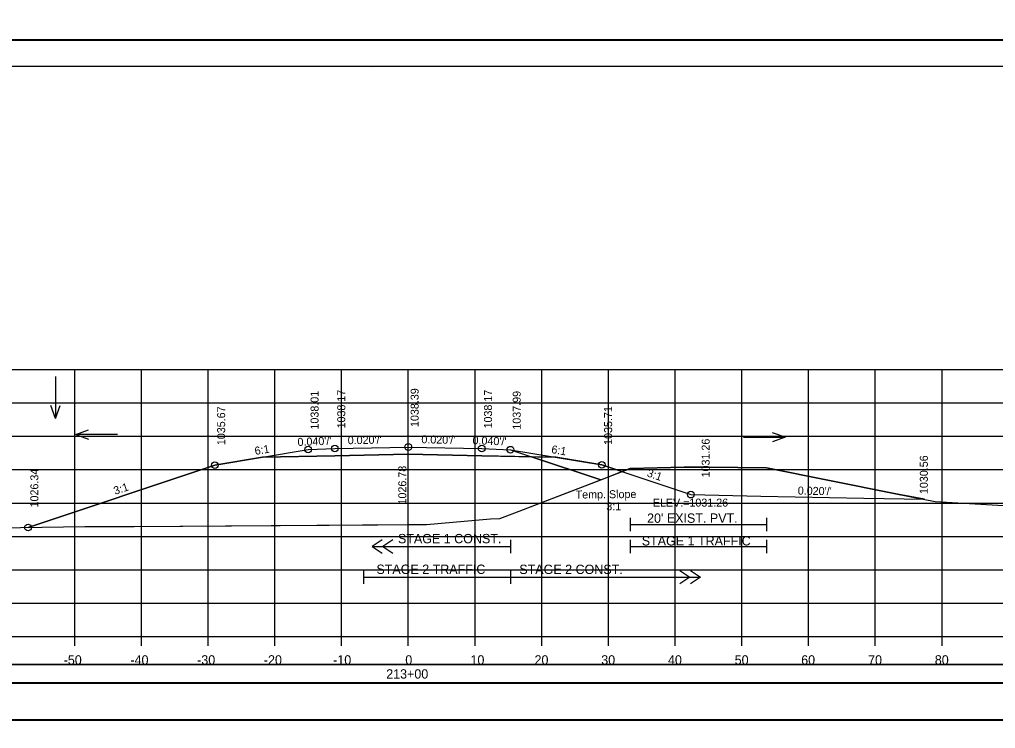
# Model space of a CAD drawing. Extents: x 1370565 to 1374448, y 301010 to 304637.
# Drawn here: x 1373310.5 to 1373456.8, y 302261.9 to 302368.1 of the extents above; entities that cross this region are included whole.
import ezdxf

# ---------------------------------------------------------------- set-up
doc = ezdxf.new("R2010")
doc.units = 0
for name, color, linetype in [('Default', 7, 'Continuous'), ('R_Alt Surface', 7, 'Continuous'), ('R_Axis', 7, 'Continuous'), ('R_Axis Annot', 7, 'Continuous'), ('R_Border', 7, 'Continuous'), ('R_Contours', 7, 'Continuous'), ('R_Drive', 7, 'Continuous'), ('R_Exist Surface', 7, 'Continuous'), ('R_Fin Surface', 7, 'Continuous'), ('R_Grid', 7, 'Continuous'), ('R_No Plot', 7, 'Continuous'), ('R_Water', 7, 'Continuous'), ('R_Water Annot', 7, 'Continuous'), ('R_Xsect Elev', 7, 'Continuous'), ('R_Xsect Slope', 7, 'Continuous')]:
    doc.layers.add(name, color=color, linetype=linetype)

msp = doc.modelspace()

# ---------------------------------------------------------------- linework, layer by layer
at = {"layer": 'Default'}
for points in [[(1373219.61, 302268.69), (1373518.02, 302268.69), (1373518.02, 302271.39), (1373219.61, 302271.39)], [(1373219.61, 302263.11), (1373518.02, 302263.11), (1373518.02, 302268.63), (1373219.61, 302268.63)]]:
    msp.add_lwpolyline(points, close=True, dxfattribs=at)
at = {"layer": 'R_Alt Surface'}
for points in [[(1373346.97, 302302.52), (1373357.81, 302302.73), (1373368.81, 302302.95), (1373379.81, 302302.73), (1373390.91, 302302.51)], [(1373364.9, 302290.14), (1373363.4, 302289.14), (1373364.9, 302288.14)], [(1373363.4, 302289.14), (1373384.11, 302289.14)], [(1373366.5, 302290.14), (1373365, 302289.14), (1373366.5, 302288.14)], [(1373362.11, 302285.56), (1373362.11, 302283.56)], [(1373362.11, 302284.56), (1373384.11, 302284.56)], [(1373384.11, 302285.56), (1373384.11, 302283.56)], [(1373384.11, 302285.56), (1373384.11, 302283.56)], [(1373384.11, 302284.56), (1373412.6, 302284.56)], [(1373409.5, 302285.56), (1373411, 302284.56), (1373409.5, 302283.56)], [(1373411.1, 302285.56), (1373412.6, 302284.56), (1373411.1, 302283.56)]]:
    msp.add_lwpolyline(points, dxfattribs=at)
at = {"layer": 'R_Axis'}
for p, q in [((1373218.81, 302275.65), (1373518.81, 302275.65)), ((1373318.81, 302274.25), (1373318.81, 302275.65)), ((1373328.81, 302274.25), (1373328.81, 302275.65)), ((1373338.81, 302274.25), (1373338.81, 302275.65)), ((1373348.81, 302274.25), (1373348.81, 302275.65)), ((1373358.81, 302274.25), (1373358.81, 302275.65)), ((1373368.81, 302274.25), (1373368.81, 302275.65)), ((1373378.81, 302274.25), (1373378.81, 302275.65)), ((1373388.81, 302274.25), (1373388.81, 302275.65)), ((1373398.81, 302274.25), (1373398.81, 302275.65)), ((1373408.81, 302274.25), (1373408.81, 302275.65)), ((1373418.81, 302274.25), (1373418.81, 302275.65)), ((1373428.81, 302274.25), (1373428.81, 302275.65)), ((1373438.81, 302274.25), (1373438.81, 302275.65)), ((1373448.81, 302274.25), (1373448.81, 302275.65))]:
    msp.add_line(p, q, dxfattribs=at)
for points in [[(1373402.08, 302293.45), (1373402.08, 302291.45)], [(1373422.5, 302293.45), (1373422.5, 302291.45)], [(1373402.08, 302292.45), (1373422.5, 302292.45)], [(1373384.11, 302290.14), (1373384.11, 302288.14)], [(1373402.08, 302290.14), (1373402.08, 302288.14)], [(1373402.08, 302289.14), (1373422.5, 302289.14)], [(1373422.5, 302290.14), (1373422.5, 302288.14)]]:
    msp.add_lwpolyline(points, dxfattribs=at)
at = {"layer": 'R_Border'}
for p, q in [((1373210.81, 302361.11), (1373526.99, 302361.11)), ((1373363.33, 302360.85), (1373363.33, 302360.85)), ((1373363.33, 302360.85), (1373363.33, 302360.85))]:
    msp.add_line(p, q, dxfattribs=at)
at = {"layer": 'R_Contours'}
for p, q in [((1373346.97, 302302.52), (1373339.81, 302301.32)), ((1373397.65, 302299.13), (1373387.29, 302302.58)), ((1373390.91, 302302.51), (1373387.29, 302302.58)), ((1373387.29, 302302.58), (1373397.65, 302299.13)), ((1373397.65, 302299.13), (1373400.83, 302300.35)), ((1373400.83, 302300.35), (1373411.17, 302296.91))]:
    msp.add_line(p, q, dxfattribs=at)
for points in [[(1373387.29, 302302.58), (1373379.81, 302302.73), (1373368.81, 302302.95), (1373357.81, 302302.73), (1373346.97, 302302.52)], [(1373400.83, 302300.35), (1373397.81, 302301.36), (1373390.91, 302302.51)], [(1373339.81, 302301.32), (1373336.37, 302300.17), (1373331.58, 302298.58), (1373319.49, 302294.55), (1373311.81, 302291.99)], [(1373446.17, 302296.21), (1373441.9, 302297.01), (1373422.5, 302300.9), (1373413.89, 302301.01), (1373411.85, 302301.04), (1373410.16, 302301), (1373402.08, 302300.84), (1373400.83, 302300.35)], [(1373311.81, 302291.99), (1373313.93, 302292.02), (1373320.33, 302292.12), (1373327.73, 302292.13), (1373368.81, 302292.43), (1373371.56, 302292.45), (1373381.12, 302293.26), (1373382.52, 302293.32), (1373384.77, 302294.16), (1373397.65, 302299.13)], [(1373411.17, 302296.91), (1373421.67, 302296.7), (1373437.1, 302296.39), (1373446.17, 302296.21)]]:
    msp.add_lwpolyline(points, dxfattribs=at)
at = {"layer": 'R_Drive'}
for points in [[(1373219.61, 302268.74), (1373518.02, 302268.74), (1373518.02, 302271.45), (1373219.61, 302271.45)], [(1373219.61, 302263.22), (1373518.02, 302263.22), (1373518.02, 302268.74), (1373219.61, 302268.74)]]:
    msp.add_lwpolyline(points, close=True, dxfattribs=at)
at = {"layer": 'R_Exist Surface'}
msp.add_lwpolyline([(1373268.65, 302291.32), (1373313.93, 302292.02), (1373320.33, 302292.12), (1373327.73, 302292.13), (1373371.56, 302292.45), (1373381.12, 302293.26), (1373382.52, 302293.32), (1373384.77, 302294.16), (1373402.08, 302300.84), (1373410.16, 302301), (1373411.85, 302301.04), (1373413.89, 302301.01), (1373422.5, 302300.9), (1373441.9, 302297.01), (1373447.77, 302295.9), (1373463.18, 302294.99), (1373467.23, 302294.76), (1373469.74, 302294.76), (1373506.89, 302294.78), (1373511.29, 302294.84), (1373516.55, 302294.89), (1373518.81, 302294.87)], dxfattribs=at)
at = {"layer": 'R_Fin Surface'}
msp.add_line((1373384.11, 302303.64), (1373397.65, 302299.13), dxfattribs=at)
msp.add_lwpolyline([(1373311.81, 302291.99), (1373319.49, 302294.55), (1373331.58, 302298.58), (1373336.37, 302300.17), (1373339.81, 302301.32), (1373353.81, 302303.66), (1373357.81, 302303.82), (1373368.81, 302304.04), (1373379.81, 302303.82), (1373384.11, 302303.64), (1373397.81, 302301.36), (1373411.17, 302296.91), (1373421.67, 302296.7), (1373437.1, 302296.39), (1373446.17, 302296.21)], dxfattribs=at)
at = {"layer": 'R_Grid'}
for p, q in [((1373218.81, 302315.65), (1373518.81, 302315.65)), ((1373318.81, 302275.65), (1373318.81, 302315.65)), ((1373328.81, 302275.65), (1373328.81, 302315.65)), ((1373338.81, 302275.65), (1373338.81, 302315.65)), ((1373348.81, 302275.65), (1373348.81, 302315.65)), ((1373358.81, 302275.65), (1373358.81, 302315.65)), ((1373368.81, 302275.65), (1373368.81, 302315.65)), ((1373378.81, 302275.65), (1373378.81, 302315.65)), ((1373388.81, 302275.65), (1373388.81, 302315.65)), ((1373398.81, 302275.65), (1373398.81, 302315.65)), ((1373408.81, 302275.65), (1373408.81, 302315.65)), ((1373418.81, 302275.65), (1373418.81, 302315.65)), ((1373428.81, 302275.65), (1373428.81, 302315.65)), ((1373438.81, 302275.65), (1373438.81, 302315.65)), ((1373448.81, 302275.65), (1373448.81, 302315.65)), ((1373218.81, 302310.65), (1373518.81, 302310.65)), ((1373218.81, 302305.65), (1373518.81, 302305.65)), ((1373218.81, 302300.65), (1373518.81, 302300.65)), ((1373218.81, 302295.65), (1373518.81, 302295.65)), ((1373218.81, 302290.65), (1373518.81, 302290.65)), ((1373218.81, 302285.65), (1373518.81, 302285.65)), ((1373218.81, 302280.65), (1373518.81, 302280.65)), ((1373218.81, 302275.65), (1373518.81, 302275.65))]:
    msp.add_line(p, q, dxfattribs=at)
at = {"layer": 'R_No Plot'}
for p, q in [((1373198.41, 302365.01), (1373531.75, 302365.01)), ((1373198.41, 302365), (1373531.75, 302365))]:
    msp.add_line(p, q, dxfattribs=at)
for points in [[(1373198.41, 302578.34), (1373531.75, 302578.34), (1373531.75, 302365.01), (1373198.41, 302365.01)], [(1373198.41, 302365), (1373531.75, 302365), (1373531.75, 302151.67), (1373198.41, 302151.67)], [(1373444.73, 302361.11), (1373464.35, 302361.11), (1373464.35, 302351.23), (1373480.47, 302351.23), (1373503.67, 302351.23), (1373503.67, 302326.9), (1373526.99, 302326.9), (1373526.99, 302155.65), (1373210.81, 302155.65), (1373210.81, 302361.11)]]:
    msp.add_lwpolyline(points, close=True, dxfattribs=at)
for centre in [(1373353.81, 302303.66), (1373357.81, 302303.82), (1373368.81, 302304.04), (1373379.81, 302303.82), (1373384.11, 302303.64), (1373339.81, 302301.32), (1373397.81, 302301.36), (1373411.17, 302296.91), (1373311.81, 302291.99)]:
    msp.add_circle(centre, 0.5, dxfattribs=at)
at = {"layer": 'R_Water Annot'}
for p, q in [((1373315.92, 302314.6), (1373315.92, 302308.32)), ((1373315.92, 302308.32), (1373315.22, 302310.24)), ((1373315.92, 302308.32), (1373316.62, 302310.24)), ((1373318.96, 302305.93), (1373320.88, 302306.63)), ((1373325.24, 302305.93), (1373318.96, 302305.93)), ((1373318.96, 302305.93), (1373320.88, 302305.23)), ((1373419.03, 302305.5), (1373425.32, 302305.5)), ((1373425.32, 302305.5), (1373423.39, 302306.18)), ((1373425.32, 302305.5), (1373423.39, 302304.81))]:
    msp.add_line(p, q, dxfattribs=at)
at = {"layer": 'R_Xsect Elev'}
msp.add_line((1373368.81, 302292.43), (1373368.81, 302302.43), dxfattribs=at)

# ---------------------------------------------------------------- texts
at = {"layer": 'R_Axis Annot'}
for s, p in [("20' EXIST. PVT.", (1373404.6, 302292.69)), ('-50', (1373317.16, 302271.45)), ('-40', (1373327.16, 302271.45)), ('-30', (1373337.16, 302271.45)), ('-20', (1373347.16, 302271.45)), ('-10', (1373357.55, 302271.45)), ('0', (1373368.36, 302271.45)), ('10', (1373378.13, 302271.45)), ('20', (1373387.73, 302271.45)), ('30', (1373397.73, 302271.45)), ('40', (1373407.73, 302271.45)), ('50', (1373417.73, 302271.45)), ('60', (1373427.7, 302271.45)), ('70', (1373437.73, 302271.45)), ('80', (1373447.73, 302271.45)), ('213+00', (1373365.5, 302269.35))]:
    msp.add_text(s, height=1.4, dxfattribs=at).set_placement(p)
at = {"layer": 'R_Water'}
for s, p in [('STAGE 1 CONST.', (1373367.26, 302289.62)), ('STAGE 1 TRAFFIC', (1373403.8, 302289.29)), ('STAGE 2 TRAFFIC', (1373364.03, 302285.03)), ('STAGE 2 CONST.', (1373385.45, 302285.02))]:
    msp.add_text(s, height=1.4, dxfattribs=at).set_placement(p)
at = {"layer": 'R_Xsect Elev'}
for s, p in [('1038.01', (1373355.36, 302306.66)), ('1038.17', (1373359.36, 302306.82)), ('1038.39', (1373370.36, 302307.04)), ('1038.17', (1373381.36, 302306.82)), ('1037.99', (1373385.66, 302306.64)), ('1035.67', (1373341.36, 302304.32)), ('1035.71', (1373399.36, 302304.36)), ('1031.26', (1373413.98, 302299.49)), ('1030.56', (1373446.68, 302296.99)), ('1026.34', (1373313.36, 302294.99)), ('1026.78', (1373368.51, 302295.43))]:
    msp.add_text(s, height=1.2, rotation=90, dxfattribs=at).set_placement(p)
msp.add_text('ELEV.=1031.26', height=1.2, dxfattribs=at).set_placement((1373405.46, 302295.11))
at = {"layer": 'R_Xsect Slope'}
for s, rotation, p in [("0.040'/'", 2.2906, (1373352.23, 302304.19)), ("0.020'/'", 1.1458, (1373359.74, 302304.45)), ("0.020'/'", 358.8542, (1373370.76, 302304.6)), ("0.040'/'", 357.7094, (1373378.42, 302304.47)), ('6:1', 9.4623, (1373345.88, 302302.84)), ('6:1', 350.5377, (1373390.19, 302303.14)), ('3:1', 341.5651, (1373404.49, 302299.66)), ('3:1', 18.4349, (1373324.87, 302296.87)), ('Temp. Slope ', 0.4964, (1373393.9, 302296.32)), ("0.020'/'", 358.8542, (1373427.18, 302296.92)), ('3:1', 0.4964, (1373398.49, 302294.56))]:
    msp.add_text(s, height=1.2, rotation=rotation, dxfattribs=at).set_placement(p)

doc.saveas('drawing.dxf')
